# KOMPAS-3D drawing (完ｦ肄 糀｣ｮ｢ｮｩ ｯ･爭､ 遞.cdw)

Referenced files in C:\Documents and Settings\GooDMaN\Мои документы\Мои работы для шараги\Чертежи для шараги\: Кожух.frw
Referenced files: Кожух тяговой передачи.cdw
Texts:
  Вставь свой шифр
  Кожух  тяговой передачи
  GooDMaN
  Домашний пк
  Текст на чертеже
  Размерные надписи
  Шероховатость
  Линия-выноска #1
  Линия-выноска #2
  Линия-выноска #3
  Отклонения формы и база
  Заголовок таблицы
  Ячейка таблицы
  Стрелка вида
  Обозначение изменения
  Фигурная скобка
  Номер узла
  Марка координационной оси
  VRCB
  Выносная надпись
  Обозначение узла
  Марка/позиционное обозначение с линией-выноской
  Марка/позиционное обозначение на линии
  Марка/позиционное обозначение без линии-выноски
  Слой 1
  Кожух
  тяговой передачи
  Иванов
  ПУ-1 гр. № 1
  ПЭР.30.4.00.00.10.ВО-
Dimensions and other numbers on the sheet: 7; 1; 0; 2; 3; 4; 5; 6; 8; 9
